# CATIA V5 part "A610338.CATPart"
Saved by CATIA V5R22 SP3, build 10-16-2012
Part number: D38999/26TH35PA
Revision: A
Definition: A610338
Nomenclature: CONNECTOR, ELEC, PLUG, CIRCULAR, THD, STR, REM CRP CONT
Source: bought
Description: CONNECTOR, ELEC, PLUG, CIRCULAR, THD, STR, REM CRP CONT
Publications: "Logical Termination.1", "Logical Pin.1", "CCP", "CCP_generated(CCP)", "Coincidence_generated(CCP)", "CCP Orientation_generated(CCP)", "BCP", "BCP_generated(BCP)", "Face_generated(BCP)", "BaCP", "BaCP_generated(BaCP)", "BaCP Orientation_generated(BaCP)"
Material "Density=.1010": density 2795.67 kg/m3
Bounding box of the stored display mesh (mm): x -33.16 to 0, y -22.264 to 22.264, z -22.43 to 22.43
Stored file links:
  C:\Users\u305772\OneDrive - Gulfstream Aerospace\AD PAG\Harness\A610338.CATPart
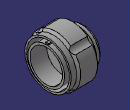
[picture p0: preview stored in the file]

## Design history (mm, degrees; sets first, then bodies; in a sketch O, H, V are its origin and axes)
Parameters
  PartNumber = "D38999/26TH35PA"
  OtherKeywords = "CONNECTORS, ELECTRICAL, PLUG, CIRCULAR, THREADED, STRAIGHT, REMOVABLE CRIMP CONTACTS SERIES III, METRIC"
  Comments = "DD THD: 1.5, VV THD: M34x1.0-6g 0.100R, NICKEL FLUOROCARBON POLYMER OVER A SUITABLE UNDERPLATE (CONDUCTIVE) -65 DEG C TO +175 DEG C, PIN"
  CAGECode = "96906"
  WeightComment = "CALCULATED FROM CATIA"
  WeightSource = "Calculated"
  Volume = 2.82225e-05 (volume) {= smartVolume(Body1)}
  Density = 2795.67 (density)
  Weight = 0.13638
AxisSystem1: origin (0, 0, 0), X (1, 0, 0), Y (0, 1, 0), Z (0, 0, 1)
Set1
  Point1 "CCP": type Center, Curve edge [face of Shaft1 from Sketch1.L2 | face of Shaft1 from Sketch1.L1]
  Point2 "BaCP": type Center, Curve edge [face of Shaft1 from Sketch1.L17 | face of Shaft1 from Sketch1.L16]
  Point3 "BCP": type Center, Curve edge [face of Shaft1 from Sketch1.L19 | face of Shaft1 from Sketch1.L18]
  Point4: (0, 0, 3.175), relative to Point1, in AxisSystem1
  Point5: (0, 0, 3.175), relative to Point2, in AxisSystem1
  Line1 "Coincidence": type PtPt, FirstPoint Point1, SecondPoint Point3
  Line2 "CCP Orientation": type PtPt, FirstPoint Point1, SecondPoint Point4
  Line3 "BaCP Orientation": type PtPt, FirstPoint Point2, SecondPoint Point5
Body1 (main body)
  Sketch1 on ZX plane of AxisSystem1, origin (0, 0, 0), H (1, 0, 0), V (0, 0, 1)
    point P1 (-14.565, 0)
    line L1 (-14.565, 0) -> (-14.565, 14.175)
    point P2 (-14.565, 14.175)
    line L2 (-14.565, 14.175) -> (-15.01, 14.175)
    point P3 (-15.01, 14.175)
    line L3 (-15.01, 14.175) -> (-15.01, 14.385)
    point P4 (-15.01, 14.385)
    line L4 (-15.01, 14.385) -> (0, 14.385)
    point P5 (0, 14.385)
    line L5 (0, 14.385) -> (0, 16.2575)
    point P6 (0, 16.2575)
    line L6 (0, 16.2575) -> (-15.01, 16.2575)
    point P7 (-15.01, 16.2575)
    line L7 (-15.01, 16.2575) -> (-15.01, 19.05)
    point P8 (-15.01, 19.05)
    line L8 (-15.01, 19.05) -> (-1.54, 19.05)
    point P9 (-1.54, 19.05)
    line L9 (-1.54, 19.05) -> (-1.54, 20.55)
    point P10 (-1.54, 20.55)
    line L10 (-1.54, 20.55) -> (-6.24, 20.55)
    point P11 (-6.24, 20.55)
    line L11 (-6.24, 20.55) -> (-8.14, 22.45)
    point P12 (-8.14, 22.45)
    line L12 (-8.14, 22.45) -> (-23, 22.45)
    point P13 (-23, 22.45)
    line L13 (-23, 22.45) -> (-23, 17)
    point P14 (-23, 17)
    line L14 (-23, 17) -> (-27.74, 17)
    point P15 (-27.74, 17)
    line L15 (-27.74, 17) -> (-28.46, 16.28)
    point P16 (-28.46, 16.28)
    line L16 (-28.46, 16.28) -> (-31, 16.28)
    point P17 (-31, 16.28)
    line L17 (-31, 16.28) -> (-31, 14.565)
    point P18 (-31, 14.565)
    line L18 (-31, 14.565) -> (-33.16, 14.565)
    point P19 (-33.16, 14.565)
    line L19 (-33.16, 14.565) -> (-33.16, 0)
    point P20 (-33.16, 0)
    axis line L20 (-33.16, 0) -> (-14.565, 0)
    point P21 (-14.565, -14.175)
    point P22 (-14.565, 0)
    construction line L21 (-14.565, 0) -> (-14.565, -14.175)
    point P23 (-15.01, -14.175)
    construction line L22 (-14.565, -14.175) -> (-15.01, -14.175)
    point P24 (-15.01, -14.385)
    construction line L23 (-15.01, -14.175) -> (-15.01, -14.385)
    point P25 (0, -14.385)
    construction line L24 (-15.01, -14.385) -> (0, -14.385)
    point P26 (0, -16.2575)
    construction line L25 (0, -14.385) -> (0, -16.2575)
    point P27 (-15.01, -16.2575)
    construction line L26 (0, -16.2575) -> (-15.01, -16.2575)
    point P28 (-15.01, -19.05)
    construction line L27 (-15.01, -16.2575) -> (-15.01, -19.05)
    point P29 (-1.54, -19.05)
    construction line L28 (-15.01, -19.05) -> (-1.54, -19.05)
    point P30 (-1.54, -20.55)
    construction line L29 (-1.54, -19.05) -> (-1.54, -20.55)
    point P31 (-6.24, -20.55)
    construction line L30 (-1.54, -20.55) -> (-6.24, -20.55)
    point P32 (-8.14, -22.45)
    construction line L31 (-6.24, -20.55) -> (-8.14, -22.45)
    point P33 (-23, -22.45)
    construction line L32 (-8.14, -22.45) -> (-23, -22.45)
    point P34 (-23, -17)
    construction line L33 (-23, -22.45) -> (-23, -17)
    point P35 (-27.74, -17)
    construction line L34 (-23, -17) -> (-27.74, -17)
    point P36 (-28.46, -16.28)
    construction line L35 (-27.74, -17) -> (-28.46, -16.28)
    point P37 (-31, -16.28)
    construction line L36 (-28.46, -16.28) -> (-31, -16.28)
    point P38 (-31, -14.565)
    construction line L37 (-31, -16.28) -> (-31, -14.565)
    point P39 (-33.16, -14.565)
    construction line L38 (-31, -14.565) -> (-33.16, -14.565)
    point P40 (-33.16, 0)
    construction line L39 (-33.16, -14.565) -> (-33.16, 0)
    distance L9 P11 = 4.7
    distance L10 L30 = 41.1
    distance L12 L32 = 44.9
    distance L5 L17 = 31
    distance L2 L22 = 28.35
    angle L16 L15 = 45
    angle L10 L11 = 45
    distance L5 L7 = 15.01
    distance L6 L26 = 32.515
    distance L24 L4 = 28.77
    distance L3 L1 = 0.445
    distance L8 L28 = 38.1
    distance L7 L9 = 13.47
    distance L17 L13 = 8
    distance L17 L19 = 2.16
    distance L38 L18 = 29.13
    distance L36 L16 = 32.56
    distance L34 L14 = 34
    distance L17 P16 = 2.54
    coincidence: P1 H, P5 V, P20 H, L7 L3
    vertical: L1 V, L3 V, L5 V, L7 V, L9 V, L13 V, L17 V, L19 V
    horizontal: L2 H, L4 H, L6 H, L8 H, L10 H, L12 H, L14 H, L16 H, L18 H, L20 H
    symmetry: P2 P21 L20, P1 P22 L20, L1 L21 L20, P3 P23 L20, L2 L22 L20, P4 P24 L20, L3 L23 L20, P5 P25 L20, L4 L24 L20, P6 P26 L20, L5 L25 L20, P7 P27 L20, L6 L26 L20, P8 P28 L20, L7 L27 L20, P9 P29 L20, L8 L28 L20, P10 P30 L20, L9 L29 L20, P11 P31 L20, L10 L30 L20, P12 P32 L20, L11 L31 L20, P13 P33 L20, L12 L32 L20, P14 P34 L20, L13 L33 L20, P15 P35 L20, L14 L34 L20, P16 P36 L20, L15 L35 L20, P17 P37 L20, L16 L36 L20, P18 P38 L20, L17 L37 L20, P19 P39 L20, L18 L38 L20, P20 P40 L20, L19 L39 L20
  Shaft1: profile Sketch1, axis Sketch1.L20, angle 360
  Sketch2 on face of Shaft1 from Sketch1.L5, origin (0, 0, 0), H (0, 1, 0), V (0, 0, 1)
    construction circle A1 centre (0, 0) radius 20.85
    construction line L1 (-20.85, 0) -> (20.85, 0)
    point P1 (-20.85, 0)
    point P2 (20.85, 0)
    arc A2 centre (17.8223, 17.8223) radius 4.3546 from (13.4699, 17.9601) to (17.9601, 13.4699) ccw
    arc A3 centre (0, 0) radius 22.45 from (17.9601, 13.4699) to (13.4699, 17.9601) ccw
    construction line L2 (0, 0) -> (17.8223, 17.8223)
    reference projected circle E1 centre (0, 0) radius 22.45 from edge [face of Shaft1 from Sketch1.L12 | face of Shaft1 from Sketch1.L11]
    point P4 (17.9601, 13.4699)
    point P5 (13.4699, 17.9601)
    length L1 = 41.7
    angle L1 L2 = 45
    distance P5 P4 = 6.35
    coincidence: P1 A1, P1 H, P2 A1
    horizontal: L1 H
    tangency: A2 A1, A3 E1
  Pocket1: profile Sketch2, direction (-1, 0, 0), through (limit type 6)
  CircPattern1: of Pocket1, instances 4, angular step 90, axis from face of Shaft1 from Sketch1.L9
  Sketch3 on face of Shaft1 from Sketch1.L5, origin (0, 0, 0), H (0, 1, 0), V (0, 0, 1)
    arc A1 centre (0, 0) radius 16.2575 from (1.27, 16.2078) to (-1.27, 16.2078) ccw
    line L1 (1.27, 17.2182) -> (1.27, 16.2078)
    line L2 (-1.27, 16.2078) -> (-1.27, 17.2182)
    point P1 (1.27, 16.2078)
    point P2 (-1.27, 16.2078)
    reference projected circle E1 centre (0, 0) radius 16.2575 from edge [face of Shaft1 from Sketch1.L6 | face of Shaft1 from Sketch1.L5]
    point P3 (-1.27, -16.2078)
    point P4 (1.27, -16.2078)
    construction arc A2 centre (0, 0) radius 16.2575 from (1.27, -16.2078) to (-1.27, -16.2078) cw
    construction line L3 (-1.27, -16.2078) -> (-1.27, -17.2182)
    construction line L4 (1.27, -17.2182) -> (1.27, -16.2078)
    arc A3 centre (0, 0) radius 17.265 from (1.27, 17.2182) to (-1.27, 17.2182) ccw
    point P6 (1.27, 17.2182)
    point P7 (-1.27, 17.2182)
    point P8 (-1.27, -17.2182)
    point P9 (1.27, -17.2182)
    construction arc A4 centre (0, 0) radius 17.265 from (1.27, -17.2182) to (-1.27, -17.2182) cw
    construction line L5 (0, 17.265) -> (0, -17.265)
    point P11 (0, 17.265)
    point P12 (0, -17.265)
    distance L2 L1 = 2.54
    length L5 = 34.53
    vertical: L1 V, L2 V, L5 V
    symmetry: L1 L2 V, P2 P3 H, P1 P4 H, A1 A2 H, L2 L3 H, L1 L4 H, P7 P8 H, P6 P9 H, A3 A4 H
    tangency: A1 E1
    coincidence: P11 A3, P11 V, P12 A4
  Pad1: profile Sketch3, direction (-1, 0, 0), length 7.24, opposite side length -0.76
